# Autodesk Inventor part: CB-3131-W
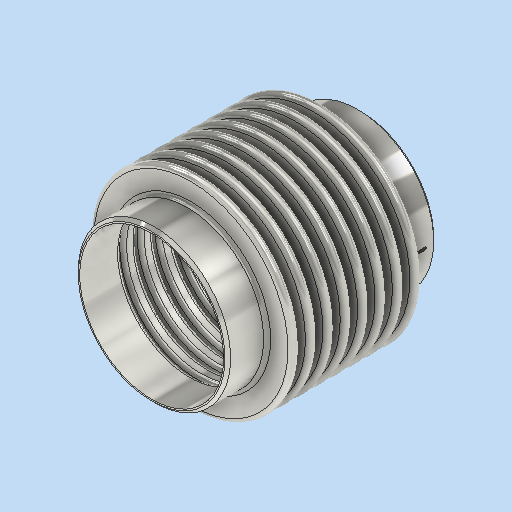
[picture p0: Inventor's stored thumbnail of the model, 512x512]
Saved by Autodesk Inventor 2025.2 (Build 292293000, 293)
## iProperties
Company: DN.RU
Created: 2026-04
Part Number: CB-3131-W
Material: Типовые
Document SubType Name: Modeling
Designer: DN.RU
Density: 4.24032 g/cm^3
Appearance: По умолчанию
Description: D140-02127
Mass: 9200 g
Surface Area: 12556.5 cm^2
Volume: 2169.65 cm^3
Author: DN.RU
Title: Компенсатор сильфонный осевой DN.ru Ду200 Ру16
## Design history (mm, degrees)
sketch "Эскиз1"
  geometry: L1 (0, 0)-(0, -150); L2 (109.5, -150)-(109.5, 0); L3 (109.5, 0)-(0, 0); L4 (109.5, 0)-(109.5, -12.5); L5 (79.5, -12.5)-(139.5, -12.5); L6 (79.5, -18.5)-(139.5, -18.5); L7 (139.5, -6.5)-(79.5, -6.5); L8 (139.5, -15.5)-(79.5, -15.5); L9 (79.5, -9.5)-(139.5, -9.5); L10 (139.5, -31.5)-(79.5, -31.5); L11 (79.5, -34.5)-(139.5, -34.5); L12 (79.5, -37.5)-(139.5, -37.5); L13 (79.5, -43.5)-(139.5, -43.5); L14 (139.5, -40.5)-(79.5, -40.5); L15 (139.5, -56.5)-(79.5, -56.5); L16 (79.5, -59.5)-(139.5, -59.5); L17 (79.5, -62.5)-(139.5, -62.5); L18 (79.5, -68.5)-(139.5, -68.5); L19 (139.5, -65.5)-(79.5, -65.5); L20 (139.5, -81.5)-(79.5, -81.5); L21 (79.5, -84.5)-(139.5, -84.5); L22 (79.5, -87.5)-(139.5, -87.5); L23 (79.5, -93.5)-(139.5, -93.5); L24 (139.5, -90.5)-(79.5, -90.5); L25 (0, -150)-(109.5, -150); L26 (109.5, -150)-(103.5, -150); L27 (109.5, -81.5)-(106.5, -81.5); L28 (103.5, -150)-(103.5, -90.5); L29 (109.5, -84.5)-(106.5, -84.5); L30 (106.5, -84.5)-(106.5, -65.5); L31 (109.5, -59.5)-(106.5, -59.5); L32 (106.5, -59.5)-(106.5, -40.5); L33 (109.5, -34.5)-(106.5, -34.5); L34 (106.5, -34.5)-(106.5, -15.5); L35 (109.5, -9.5)-(106.5, -9.5); L36 (106.5, -9.5)-(106.5, 0); A1 r 6 centre (79.5, -12.5) between (79.5, -6.5) and (79.5, -18.5); A2 r 6 centre (139.5, -12.5) between (139.5, -18.5) and (139.5, -6.5); A3 r 3 centre (79.5, -12.5) between (79.5, -9.5) and (79.5, -15.5); A4 r 3 centre (139.5, -12.5) between (139.5, -15.5) and (139.5, -9.5); A5 r 3 centre (79.5, -37.5) between (79.5, -34.5) and (79.5, -40.5); A6 r 6 centre (79.5, -37.5) between (79.5, -31.5) and (79.5, -43.5); A7 r 3 centre (139.5, -37.5) between (139.5, -40.5) and (139.5, -34.5); A8 r 6 centre (139.5, -37.5) between (139.5, -43.5) and (139.5, -31.5); A9 r 3 centre (79.5, -62.5) between (79.5, -59.5) and (79.5, -65.5); A10 r 6 centre (79.5, -62.5) between (79.5, -56.5) and (79.5, -68.5); A11 r 3 centre (139.5, -62.5) between (139.5, -65.5) and (139.5, -59.5); A12 r 6 centre (139.5, -62.5) between (139.5, -68.5) and (139.5, -56.5); A13 r 3 centre (79.5, -87.5) between (79.5, -84.5) and (79.5, -90.5); A14 r 6 centre (79.5, -87.5) between (79.5, -81.5) and (79.5, -93.5); A15 r 3 centre (139.5, -87.5) between (139.5, -90.5) and (139.5, -84.5); A16 r 6 centre (139.5, -87.5) between (139.5, -93.5) and (139.5, -81.5); 18 further points
  constraints: 80 end point, 32 point on circle, 16 centre point, 15 point on line, 6 midpoint, 5 perpendicular, 4 tangent, 3 parallel, 2 vertical, 1 horizontal, 69 other
  dimensions: "d0" = 150 distance of L1.start L1.end; "d1" = 109.5 distance of L2.start L1.end; "d3" = 12.5 distance of L2.end L4.end; "d4" = 30 distance of L4.end L5.end; "d5" = 12 diameter of A2; "d6" = 3 distance between parallel lines of L6 L8; "d9" = 25 distance of L4.end point (109.5, -37.5); "d14" = 6 distance of L2.start L26.end; "d15" = 3 distance of L27.start L27.end; "d16" = 3 distance of L29.start L29.end; "d17" = 3 distance of L31.start L31.end; "d18" = 3 distance of L33.start L33.end; "d19" = 3 distance of L35.start L35.end
revolve "Вращение1" sketch "Эскиз1" stored, may be unused: angle "d20" = 360 deg
mirror "Зеркальное отражение1"
chamfer "Фаска1" distance "d21" = 4; stored, may be unused: second distance "d22" = 2, angle "d23" = 45 deg
fillet "Сопряжение1" dims "d24" = 5
node "РабПлоскость1"
sketch "Эскиз2"
  geometry: L1 (5.733, 17.21)-(5.733, -23.181); L2 (5.733, -23.181)-(-2.398, -23.181); L3 (-2.398, -23.181)-(-2.398, 17.21); L4 (-2.398, 17.21)-(5.733, 17.21); 1 further point
  constraints: 2 other
feature "Рельеф1" sketch "Эскиз2" dims "d25" = 0.1, "d26" = 0
node "Твердое тело1"
node "Эскиз — прямоугольный массив1" dims "d9" = 25, "d12" = 10
